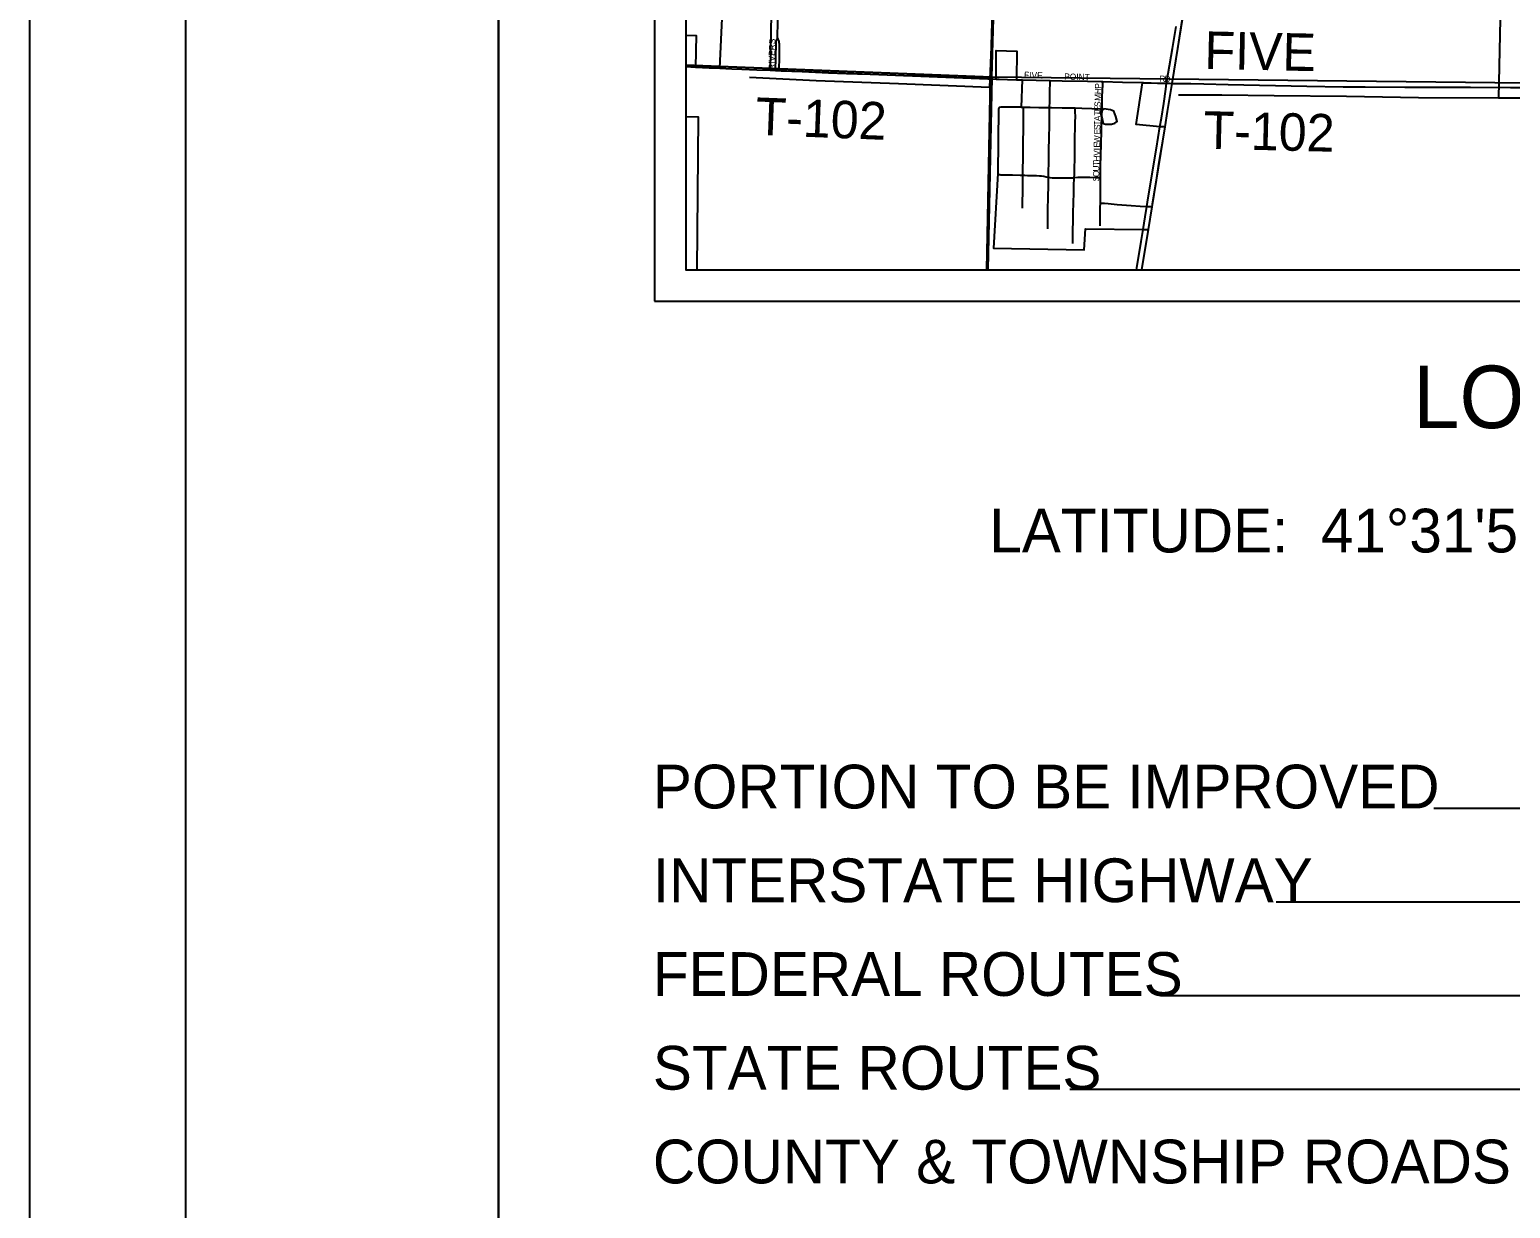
# Model space of a CAD drawing. Extents: x -5.6 to 34, y 0 to 22.
# Drawn here: x 0 to 4.739, y 11.097 to 14.869 of the extents above; entities that cross this region are included whole.
import ezdxf

# ---------------------------------------------------------------- set-up
doc = ezdxf.new("R2010")
doc.units = 0
for name, color, linetype in [('GM_X_City_Street', 7, 'Continuous'), ('GM_X_City_Street_Text', 7, 'Continuous'), ('GM_X_Corporation', 7, 'Continuous'), ('GM_X_Minor_Lake', 7, 'Continuous'), ('GM_X_Minor_River', 7, 'Continuous'), ('GM_X_Section', 7, 'Continuous'), ('GM_X_State_Route', 7, 'Continuous'), ('GM_X_Township', 7, 'Continuous'), ('GM_X_Township_Road', 7, 'Continuous'), ('GM_X_Township_Road_Text', 7, 'Continuous'), ('SH_Border', 7, 'Continuous'), ('SH_Cut_Line', 7, 'Continuous'), ('SH_Data', 7, 'Continuous'), ('SH_Text', 7, 'Continuous')]:
    doc.layers.add(name, color=color, linetype=linetype)

msp = doc.modelspace()

# ---------------------------------------------------------------- linework, layer by layer
at = {"layer": 'GM_X_City_Street'}
for points in [[(2.3933, 14.8413), (2.3964, 15.0088), (2.3964, 15.0258), (2.3962, 15.0284)], [(2.3871, 14.7385), (2.3872, 14.7413), (2.388, 14.7754), (2.3892, 14.83), (2.3893, 14.8322), (2.3897, 14.8341), (2.3906, 14.8366), (2.3916, 14.8386), (2.3933, 14.8413)], [(2.3987, 14.738), (2.3987, 14.7413), (2.3996, 14.7794), (2.4, 14.7961), (2.3994, 14.8223), (2.3991, 14.8281), (2.3985, 14.8314), (2.3977, 14.8343), (2.3967, 14.8367), (2.3953, 14.839), (2.3933, 14.8413)], [(3.1763, 14.7085), (3.2656, 14.7064)], [(3.2639, 14.6196), (3.2642, 14.6392), (3.265, 14.6755), (3.2654, 14.6969), (3.2656, 14.7064)], [(3.2656, 14.7064), (3.3045, 14.7055), (3.3853, 14.7038), (3.4291, 14.7028), (3.4341, 14.7026)], [(3.432, 14.6159), (3.4322, 14.6215), (3.4326, 14.6542), (3.4338, 14.6939), (3.4341, 14.7026)], [(3.4341, 14.7026), (3.4975, 14.701), (3.5647, 14.6996)], [(3.5647, 14.6996), (3.5895, 14.6989), (3.6178, 14.6982), (3.6384, 14.6976)], [(3.6384, 14.6976), (3.6475, 14.6973), (3.6566, 14.6969)], [(3.1732, 14.6209), (3.1808, 14.6209)], [(3.1783, 14.4034), (3.1786, 14.4183), (3.1793, 14.4596), (3.1794, 14.4724), (3.1795, 14.4839), (3.1797, 14.5004), (3.1795, 14.5096), (3.1797, 14.5185), (3.1804, 14.5414), (3.1804, 14.5592), (3.1808, 14.5852), (3.1808, 14.613), (3.1808, 14.6209)], [(3.1808, 14.6209), (3.2017, 14.6207), (3.23, 14.6203), (3.2639, 14.6196)], [(3.2602, 14.3965), (3.2602, 14.402), (3.2611, 14.4558), (3.2618, 14.4899), (3.2622, 14.5161), (3.2633, 14.5695), (3.2638, 14.6032), (3.2639, 14.6196)], [(3.2639, 14.6196), (3.2697, 14.6195), (3.3044, 14.6191), (3.3377, 14.6187), (3.3461, 14.6184)], [(3.343, 14.3956), (3.3434, 14.4044), (3.344, 14.4309), (3.3444, 14.4507), (3.3446, 14.4625), (3.3448, 14.486), (3.3451, 14.5247), (3.3458, 14.5548), (3.3463, 14.5721), (3.3464, 14.5917), (3.3459, 14.6054), (3.3461, 14.6184)], [(3.3461, 14.6184), (3.3668, 14.6178), (3.3989, 14.617), (3.4245, 14.6161), (3.432, 14.6159)], [(3.4268, 14.3962), (3.4268, 14.401), (3.4267, 14.4239), (3.4272, 14.443), (3.4276, 14.4562), (3.4284, 14.4767), (3.4289, 14.4921), (3.4293, 14.5114), (3.4297, 14.5379), (3.4301, 14.5606), (3.431, 14.5907), (3.432, 14.6159)], [(3.0993, 14.407), (3.1002, 14.4061), (3.1021, 14.4054), (3.1042, 14.405), (3.108, 14.4048), (3.117, 14.4049), (3.1339, 14.4045), (3.1457, 14.4046), (3.1695, 14.4038), (3.1783, 14.4034)], [(3.1771, 14.2974), (3.1771, 14.3141), (3.1779, 14.353), (3.1779, 14.3825), (3.1783, 14.4034)], [(3.1783, 14.4034), (3.1848, 14.4032), (3.1937, 14.4027), (3.2077, 14.4022), (3.2219, 14.4018), (3.2316, 14.4015), (3.2382, 14.4009), (3.2452, 14.3998), (3.2525, 14.3982), (3.2588, 14.3968), (3.2602, 14.3965)], [(3.2579, 14.2312), (3.2583, 14.256), (3.2583, 14.2765), (3.2586, 14.301), (3.259, 14.3246), (3.2601, 14.3783), (3.2602, 14.3965)], [(3.2602, 14.3965), (3.2652, 14.3954), (3.2717, 14.3946), (3.2798, 14.3943), (3.2897, 14.3943), (3.3004, 14.3945), (3.3079, 14.3943), (3.3162, 14.3943), (3.3295, 14.3947), (3.3379, 14.3951), (3.343, 14.3956)], [(3.3378, 14.1843), (3.3388, 14.2289), (3.3392, 14.2551), (3.3399, 14.2852), (3.3405, 14.3127), (3.3414, 14.3494), (3.3417, 14.3677), (3.343, 14.3956)], [(3.343, 14.3956), (3.3539, 14.3966), (3.3672, 14.397), (3.3812, 14.3965), (3.3922, 14.3965), (3.41, 14.3964), (3.4213, 14.3962), (3.4268, 14.3962)], [(3.4264, 14.3141), (3.4268, 14.3399), (3.4268, 14.3536), (3.4268, 14.3634), (3.4268, 14.3745), (3.4268, 14.3882), (3.4268, 14.3962)], [(3.4256, 14.2407), (3.4255, 14.2527), (3.426, 14.2659), (3.426, 14.2736), (3.426, 14.2881), (3.426, 14.2996), (3.4264, 14.3134), (3.4264, 14.3141)], [(3.4264, 14.3141), (3.4395, 14.3133), (3.4513, 14.3125), (3.48, 14.3098), (3.5247, 14.3062), (3.5533, 14.3043), (3.5747, 14.3033)], [(3.5747, 14.3033), (3.5887, 14.3026), (3.5919, 14.3024)]]:
    msp.add_lwpolyline(points, dxfattribs=at)
at = {"layer": 'GM_X_Corporation'}
for points in [[(2.3725, 14.9211), (2.3697, 14.7394), (3.0935, 14.7111), (3.0931, 14.8021), (3.1592, 14.8004), (3.1581, 14.7087), (3.1763, 14.7085), (3.1732, 14.6209), (3.1079, 14.6213), (3.1028, 14.6204), (3.1006, 14.6156), (3.0986, 14.4086), (3.0848, 14.1696), (3.3743, 14.1643), (3.3787, 14.2314), (3.5632, 14.2299), (3.58, 14.2293), (3.5919, 14.3024), (3.6335, 14.5579), (3.6169, 14.5578), (3.5411, 14.565), (3.5614, 14.699), (3.6566, 14.6969), (3.8322, 15.7856)], [(2.1, 14.9372), (2.1, 14.8511), (2.1325, 14.8508), (2.1313, 14.7492), (2.2086, 14.7456), (2.2168, 14.9277)]]:
    msp.add_lwpolyline(points, dxfattribs=at)
msp.add_lwpolyline([(2.1358, 14.1), (2.1406, 14.5888), (2.1, 14.5901), (2.1, 14.1)], close=True, dxfattribs=at)
at = {"layer": 'GM_X_Minor_Lake'}
msp.add_line((3.4566, 14.5664), (3.4622, 14.5671), dxfattribs=at)
msp.add_lwpolyline([(3.4622, 14.5671), (3.4727, 14.5701), (3.48, 14.5747), (3.4764, 14.5916), (3.4696, 14.6086), (3.4593, 14.6129), (3.4371, 14.6158), (3.4256, 14.6057), (3.4323, 14.5839), (3.4359, 14.5685), (3.4431, 14.5668), (3.4566, 14.5664)], dxfattribs=at)
at = {"layer": 'GM_X_Minor_River'}
for points in [[(3.1727, 18.2606), (3.156, 17.9033), (3.1519, 17.6042), (3.1419, 17.1897), (3.1336, 16.8819), (3.1308, 16.8323), (3.1221, 16.5076), (3.1169, 16.2286), (3.1032, 15.8929), (3.0921, 15.5667), (3.0838, 15.1603), (3.0776, 14.8396), (3.0715, 14.6841), (2.7803, 14.6952), (2.5171, 14.7048), (2.3034, 14.7157)], [(4.7103, 15.0997), (4.7043, 14.852), (4.701, 14.6508)], [(3.6761, 14.6605), (3.815, 14.6604), (3.9826, 14.6579), (4.2141, 14.6562), (4.4447, 14.6522), (4.701, 14.6508), (5.0092, 14.6513)]]:
    msp.add_lwpolyline(points, dxfattribs=at)
at = {"layer": 'GM_X_Section'}
for points in [[(2.1, 16.9188), (2.1, 14.755), (3.0791, 14.7168), (3.1401, 16.8587)], [(3.1401, 16.8587), (5.2895, 16.8144), (5.2575, 14.6921), (3.0791, 14.7168)], [(2.1, 14.755), (2.1, 14.1), (3.0658, 14.1), (3.0791, 14.7168)], [(3.0658, 14.1), (5.2509, 14.1), (5.2575, 14.6921), (3.0791, 14.7168)]]:
    msp.add_lwpolyline(points, close=True, dxfattribs=at)
at = {"layer": 'GM_X_State_Route'}
msp.add_line((3.5589, 14.1), (3.58, 14.2293), dxfattribs=at)
for points in [[(3.6566, 14.6969), (3.6754, 14.8154), (3.6887, 14.8984), (3.7135, 15.0489)], [(3.5425, 14.1), (3.5436, 14.1069), (3.5567, 14.1907), (3.5632, 14.2299), (3.5694, 14.2704), (3.5747, 14.3033), (3.5771, 14.3171), (3.5815, 14.3432), (3.6057, 14.4902), (3.6169, 14.5578), (3.6217, 14.5861), (3.6291, 14.6324), (3.6359, 14.6791), (3.6384, 14.6976), (3.6438, 14.7283), (3.6571, 14.8082), (3.6685, 14.8787)], [(3.6416, 14.6072), (3.6566, 14.6969)], [(3.5933, 14.3109), (3.5987, 14.3436), (3.6071, 14.3953), (3.6139, 14.4381), (3.6183, 14.4639), (3.625, 14.5053), (3.6334, 14.5579), (3.6416, 14.6072)], [(3.58, 14.2293), (3.5919, 14.3024), (3.5933, 14.3109)]]:
    msp.add_lwpolyline(points, dxfattribs=at)
at = {"layer": 'GM_X_Township'}
for points in [[(3.0636, 14.1), (8.9, 14.1), (8.9, 20.9), (2.1, 20.9), (2.1, 16.9108), (2.7242, 16.8707), (3.1388, 16.8616), (3.0745, 14.7121)], [(2.1, 16.9108), (2.1, 14.1), (3.0636, 14.1), (3.0745, 14.7121), (3.1388, 16.8616), (2.7242, 16.8707)]]:
    msp.add_lwpolyline(points, close=True, dxfattribs=at)
at = {"layer": 'GM_X_Township_Road'}
msp.add_line((2.1, 14.7507), (2.1313, 14.7492), dxfattribs=at)
for points in [[(2.1313, 14.7492), (2.1751, 14.7472), (2.2086, 14.7456)], [(2.2086, 14.7456), (2.2468, 14.744), (2.2791, 14.7426), (2.3271, 14.7408), (2.3697, 14.7394)], [(2.3697, 14.7394), (2.3871, 14.7385)], [(2.3871, 14.7385), (2.3987, 14.738)], [(2.3987, 14.738), (2.4047, 14.7377), (2.4727, 14.7348), (2.5153, 14.7333), (2.5569, 14.7312), (2.614, 14.7289), (2.6489, 14.7275), (2.6897, 14.7261), (2.7442, 14.7241), (2.7965, 14.7223), (2.8351, 14.7209), (2.8611, 14.7197), (2.9235, 14.7176), (2.9669, 14.7161), (2.9912, 14.7153), (3.0156, 14.7145), (3.0511, 14.7131), (3.0695, 14.7123), (3.0824, 14.7117), (3.0935, 14.7111)], [(3.0935, 14.7111), (3.1026, 14.7107), (3.1291, 14.7097), (3.1581, 14.7087)], [(3.1581, 14.7087), (3.1763, 14.7085)], [(3.6566, 14.6969), (3.7158, 14.6962), (3.7578, 14.6953)], [(3.7578, 14.6953), (3.8357, 14.6935), (4.0873, 14.6881), (4.2029, 14.6865), (4.2738, 14.6859), (4.4012, 14.6853), (4.4708, 14.6848), (4.4885, 14.6848), (4.4977, 14.6847)], [(4.4977, 14.6847), (4.6113, 14.6845), (4.7391, 14.684), (4.843, 14.684), (5.0184, 14.6841), (5.1773, 14.6846), (5.2635, 14.6842)]]:
    msp.add_lwpolyline(points, dxfattribs=at)
at = {"layer": 'SH_Border'}
for points in [[(0.5, 21.5), (1.5, 21.5), (1.5, 0.5), (0.5, 0.5)], [(1.5, 21.5), (33.5, 21.5), (33.5, 0.5), (1.5, 0.5)]]:
    msp.add_lwpolyline(points, close=True, dxfattribs=at)
at = {"layer": 'SH_Cut_Line'}
msp.add_lwpolyline([(0, 0), (34, 0), (34, 22), (0, 22)], close=True, dxfattribs=at)
at = {"layer": 'SH_Data'}
for p, q in [((2, 21), (2, 14)), ((2.1, 20.9), (2.1, 14.1)), ((2.1, 14.1), (2.1, 14.1)), ((2.1, 14.1), (2.1, 14.1)), ((2.1, 14.1), (8.9, 14.1)), ((2, 14), (9, 14)), ((7.7, 12.3767), (4.4937, 12.3767)), ((7.7, 12.0767), (3.9895, 12.0767)), ((7.7, 11.7767), (3.6192, 11.7767)), ((7.7, 11.4767), (3.3288, 11.4767))]:
    msp.add_line(p, q, dxfattribs=at)

# ---------------------------------------------------------------- texts
at = {"layer": 'GM_X_City_Street_Text'}
for s, rotation, p in [('RIVERS', 88.8544, (2.3844, 14.7405)), ('FIVE', 358.1533, (3.182, 14.7145)), ('POINT', 358.6036, (3.3105, 14.7092)), ('P', 87.8961, (3.429, 14.6797)), ('R', 359.2228, (3.6148, 14.7021)), ('D', 355.2073, (3.6303, 14.702)), ('M', 88.5611, (3.4278, 14.641)), ('H', 87.9015, (3.4284, 14.6621)), ('T', 88.9892, (3.427, 14.5936)), ('S', 88.9892, (3.4275, 14.6217)), ('E', 88.9892, (3.4272, 14.6076)), ('S', 89.003, (3.4262, 14.5478)), ('E', 88.9618, (3.4259, 14.5337)), ('T', 88.9892, (3.4264, 14.5619)), ('A', 89.0019, (3.4267, 14.576)), ('E', 88.9892, (3.4252, 14.4915)), ('W', 88.9743, (3.4254, 14.5055)), ('H', 85.9315, (3.4234, 14.4463)), ('V', 88.7879, (3.4246, 14.465)), ('I', 89.0121, (3.425, 14.4827)), ('O', 89.847, (3.4228, 14.3974)), ('T', 88.1418, (3.4229, 14.4325)), ('U', 89.847, (3.4229, 14.415)), ('S', 89.8634, (3.4228, 14.3833))]:
    msp.add_text(s, height=0.02, rotation=rotation, dxfattribs=at).set_placement(p)
at = {"layer": 'GM_X_Township_Road_Text'}
for s, rotation, p in [('FIVE', 358.7715, (3.7585, 14.7437)), ('T-102', 357.7574, (2.3212, 14.5325)), ('T-102', 358.6035, (3.7554, 14.4884))]:
    msp.add_text(s, height=0.12, rotation=rotation, dxfattribs=at).set_placement(p)
at = {"layer": 'SH_Text'}
for s, height, p in [('LOCATION MAP', 0.2, (4.4269, 13.5938)), ('LATITUDE:  41°31\'56.78"     LONGITUDE:  83°37\'16.80"', 0.14, (3.071, 13.1959)), ('PORTION TO BE IMPROVED', 0.14, (1.9944, 12.3767)), ('INTERSTATE HIGHWAY', 0.14, (1.9944, 12.0767)), ('FEDERAL ROUTES', 0.14, (1.9944, 11.7767)), ('STATE ROUTES', 0.14, (1.9944, 11.4767)), ('COUNTY & TOWNSHIP ROADS', 0.14, (1.9944, 11.1767))]:
    msp.add_text(s, height=height, dxfattribs=at).set_placement(p)

doc.saveas('drawing.dxf')
